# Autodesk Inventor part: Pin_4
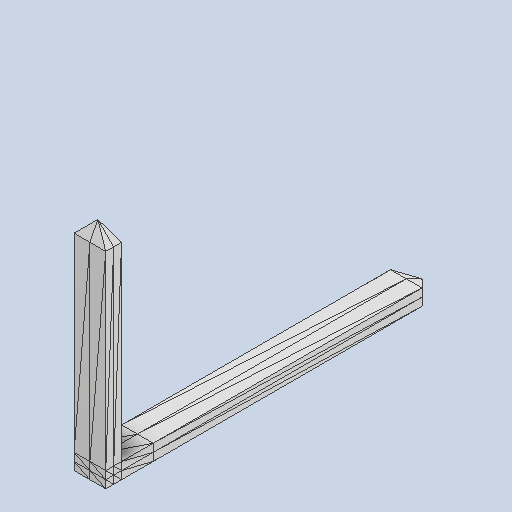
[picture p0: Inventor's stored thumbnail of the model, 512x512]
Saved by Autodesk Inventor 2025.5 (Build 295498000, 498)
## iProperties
Created: 2026-10
Part Number: Pin_4
Material: Genérico
Document SubType Name: Modeling
Designer: Luis M
Density: 1 g/cm^3
Appearance: Valor por defecto
Author: Luis M
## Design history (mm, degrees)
feature "Base1"
node "Sólido1"
